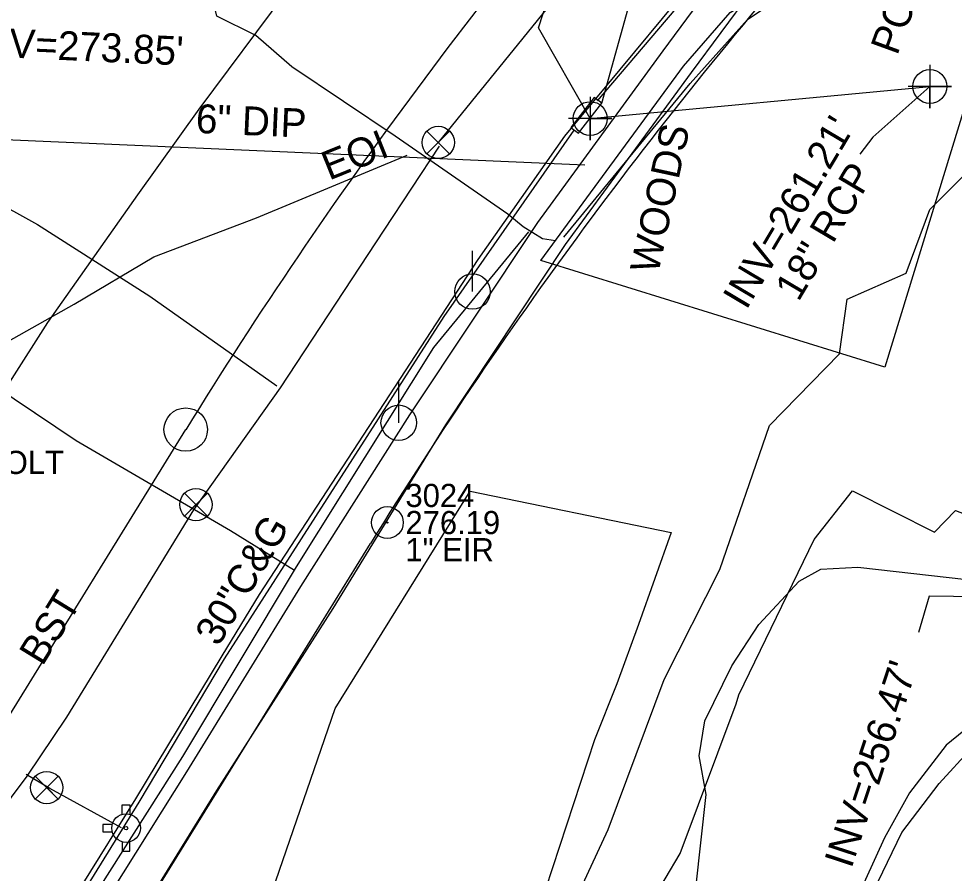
# Model space of a CAD drawing. Extents: x 2100323 to 2109811, y 740376 to 749755.
# Drawn here: x 2105562.4 to 2105691.7, y 743149.3 to 743267.5 of the extents above; entities that cross this region are included whole.
import ezdxf

# ---------------------------------------------------------------- set-up
doc = ezdxf.new("R2010")
doc.units = 0
for name, color, linetype in [('Exist Horizontal Alignment Point', 7, 'Continuous'), ('Exist Hydro Jurisdictional Stream or Body of Water', 7, 'Continuous'), ('Exist Hydro Stream or Body of Water', 7, 'Continuous'), ('Exist Other Culture Located Object Text', 7, 'Continuous'), ('Exist Property Iron Pin CELL', 7, 'Continuous'), ('Exist Property Iron Pin Cogo Comment', 7, 'Continuous'), ('Exist Property Iron Pin Cogo Elevation', 7, 'Continuous'), ('Exist Property Iron Pin Cogo Number', 7, 'Continuous'), ('Exist Right of Way Line', 7, 'Continuous'), ('Exist Roads Curbs', 7, 'Continuous'), ('Exist Roads Curbs Text', 7, 'Continuous'), ('Exist Roads EOP', 7, 'Continuous'), ('Exist Roads EOP Other', 7, 'Continuous'), ('Exist Roads EOP Other Text', 7, 'Continuous'), ('Exist Roads EOT', 7, 'Continuous'), ('Exist Roads Soil', 7, 'Continuous'), ('Exist Structure Minor Drop Inlet', 7, 'Continuous'), ('Exist Structure Minor Drop Inlet Leader', 7, 'Continuous'), ('Exist Structure Minor Pipes RCP 15 Inch Invert', 7, 'Continuous'), ('Exist Structure Minor Pipes RCP 15 Inch Leader', 7, 'Continuous'), ('Exist Structure Minor Pipes RCP 18 Inch', 7, 'Continuous'), ('Exist Structure Minor Pipes RCP 18 Inch Cogo Point CELL', 7, 'Continuous'), ('Exist Structure Minor Pipes RCP 18 Inch Invert', 7, 'Continuous'), ('Exist Structure Minor Pipes RCP 18 Inch Leader', 7, 'Continuous'), ('Exist Survey Centerline', 7, 'Continuous'), ('Exist Utilities Gas UG Line SUE LOS B', 7, 'Continuous'), ('Exist Utilities Gas UG Line SUE LOS B Text', 7, 'Continuous'), ('Exist Utilities Power Pole CELL', 7, 'Continuous'), ('Exist Utilities Sanitary Sewer UG Line', 7, 'Continuous'), ('Exist Utilities Sanitary Sewer UG Line Invert Elevation', 7, 'Continuous'), ('Exist Utilities Sanitary Sewer UG Line Text', 7, 'Continuous'), ('Exist Utilities Water Fire Hydrant CELL', 7, 'Continuous'), ('Exist Utilities Water UG Line SUE LOS B', 7, 'Continuous'), ('Exist Utilities Water Valve CELL', 7, 'Continuous'), ('Exist Vegetation Woods Line', 7, 'Continuous'), ('Exist Vegetation Woods Line Text', 7, 'Continuous')]:
    doc.layers.add(name, color=color, linetype=linetype)

msp = doc.modelspace()

# ---------------------------------------------------------------- linework, layer by layer
at = {"layer": 'Exist Horizontal Alignment Point'}
msp.add_circle((2105585.48, 743210.69), 3, dxfattribs=at)
at = {"layer": 'Exist Hydro Jurisdictional Stream or Body of Water'}
for points in [[(2105611.51, 743083.14), (2105621, 743093.76), (2105619.33, 743109.02), (2105632.97, 743131.85), (2105643.89, 743155.42), (2105651.63, 743176.14), (2105659.31, 743191.36), (2105666.16, 743211.28), (2105675.84, 743221.15), (2105676.89, 743228.75), (2105685.05, 743232.31), (2105688.33, 743241.12), (2105701.55, 743254.3), (2105697.47, 743255.64), (2105700.14, 743260.45)], [(2105661.92, 743174.03), (2105672.32, 743195.52), (2105677.64, 743202.24), (2105688.99, 743196.5), (2105691.89, 743199.49), (2105695.92, 743197.94), (2105701.75, 743199.11), (2105705.8, 743200.96), (2105708.02, 743206.18), (2105706.14, 743212.89), (2105695.44, 743219.72), (2105694.63, 743222.54), (2105697.81, 743239.29), (2105714.74, 743245.18), (2105719.05, 743249.95), (2105724.67, 743252.03)], [(2105624.08, 743074.55), (2105634.72, 743099.14), (2105632.38, 743113.28), (2105634.4, 743121.33), (2105641.37, 743131.06), (2105653.8, 743152.06), (2105661.54, 743172.79)]]:
    msp.add_lwpolyline(points, dxfattribs=at)
at = {"layer": 'Exist Hydro Stream or Body of Water'}
msp.add_lwpolyline([(2105661.54, 743172.79), (2105661.92, 743174.03), (2105661.92, 743174.03)], dxfattribs=at)
at = {"layer": 'Exist Property Iron Pin CELL'}
for radius in [2.2, 0.0707]:
    msp.add_circle((2105613.35, 743197.84), radius, dxfattribs=at)
at = {"layer": 'Exist Right of Way Line'}
msp.add_line((2105546.64, 743090.64), (2105611.01, 743194.93), dxfattribs=at)
msp.add_arc((2106150.96, 742861.67), 634.51, 138.49187, 148.31686, dxfattribs=at)
at = {"layer": 'Exist Roads Curbs'}
for points in [[(2105665.93, 743283.59), (2105661.69, 743278.93), (2105642.35, 743256.16)], [(2105639.14, 743252.1), (2105621.15, 743226.32), (2105590.78, 743179.02), (2105578.98, 743159.19), (2105564.1, 743135.08), (2105550.18, 743112.3), (2105535.32, 743088.03), (2105522.97, 743066.77), (2105512.81, 743045.05), (2105499.41, 743011.11), (2105491.13, 742988.26)]]:
    msp.add_lwpolyline(points, dxfattribs=at)
at = {"layer": 'Exist Roads EOP'}
msp.add_lwpolyline([(2105497.38, 743007.27), (2105512.22, 743045.33), (2105522.46, 743067.04), (2105534.76, 743088.24), (2105546.74, 743107.94), (2105563.57, 743135.49), (2105578.58, 743159.63), (2105590.5, 743179.39), (2105595.7, 743187.88), (2105625.9, 743234.22), (2105637.86, 743251.29), (2105661.05, 743279.27), (2105667.24, 743285.75), (2105678.58, 743289.74), (2105689.8, 743286.23)], dxfattribs=at)
at = {"layer": 'Exist Roads EOP Other'}
for points in [[(2105501.08, 743005.15), (2105511.67, 743033.08), (2105523.99, 743060.6), (2105538.57, 743086.76), (2105554.21, 743112.29), (2105569.83, 743138.17), (2105585.65, 743163.37), (2105601.37, 743188.98), (2105616.47, 743212.73), (2105634.17, 743239.33), (2105651.46, 743263.05), (2105667.68, 743285.04)], [(2105671.76, 743282.25), (2105655.36, 743260.06), (2105637.93, 743236.27), (2105621.39, 743211.36), (2105605.82, 743185.98), (2105589.75, 743160.77), (2105574.04, 743135.31), (2105558.38, 743109.45), (2105542.64, 743084.1), (2105528.3, 743058.34), (2105516.18, 743031.31)]]:
    msp.add_lwpolyline(points, dxfattribs=at)
at = {"layer": 'Exist Roads EOT'}
msp.add_lwpolyline([(2105599.31, 743271.17), (2105587.3, 743254.99), (2105578.82, 743243.14), (2105566.36, 743225.51), (2105556.13, 743209.5), (2105550.57, 743199.82)], dxfattribs=at)
at = {"layer": 'Exist Roads Soil'}
msp.add_lwpolyline([(2105679.85, 743145.42), (2105684.46, 743154.98), (2105689.6, 743161.76), (2105694.1, 743166.65), (2105698.97, 743170.49), (2105704.72, 743173.66), (2105709.92, 743175.46), (2105714.68, 743176.96), (2105721.14, 743180.41), (2105723.19, 743182.52), (2105726.27, 743186.3), (2105728.65, 743191.26), (2105730.83, 743199.74), (2105733.16, 743211.07)], dxfattribs=at)
at = {"layer": 'Exist Structure Minor Drop Inlet'}
msp.add_lwpolyline([(2105638.69, 743252.48), (2105639.75, 743251.69), (2105643, 743255.81), (2105641.93, 743256.61)], close=True, dxfattribs=at)
at = {"layer": 'Exist Structure Minor Drop Inlet Leader'}
msp.add_lwpolyline([(2105643, 743255.81), (2105648.25, 743274.78), (2105650.12, 743280.49)], dxfattribs=at)
at = {"layer": 'Exist Structure Minor Pipes RCP 15 Inch Leader'}
msp.add_lwpolyline([(2105704.96, 743187.43), (2105688.24, 743187.65), (2105686.74, 743182.63)], dxfattribs=at)
at = {"layer": 'Exist Structure Minor Pipes RCP 18 Inch'}
msp.add_line((2105641.39, 743253.7), (2105688.34, 743258.14), dxfattribs=at)
at = {"layer": 'Exist Structure Minor Pipes RCP 18 Inch Cogo Point CELL'}
for points in [[(2105688.34, 743261.14), (2105688.34, 743255.14), (2105688.34, 743258.14), (2105691.34, 743258.14), (2105685.34, 743258.14)], [(2105641.39, 743256.7), (2105641.39, 743250.7), (2105641.39, 743253.7), (2105644.39, 743253.7), (2105638.39, 743253.7)]]:
    msp.add_lwpolyline(points, dxfattribs=at)
for centre in [(2105688.34, 743258.14), (2105641.39, 743253.7)]:
    msp.add_circle(centre, 2.34, dxfattribs=at)
at = {"layer": 'Exist Structure Minor Pipes RCP 18 Inch Leader'}
for points in [[(2105641.39, 743253.7), (2105634.22, 743266.27), (2105636.09, 743271.97)], [(2105688.34, 743258.14), (2105680.45, 743251.14), (2105678.65, 743248.77)]]:
    msp.add_lwpolyline(points, dxfattribs=at)
at = {"layer": 'Exist Survey Centerline'}
msp.add_line((2105521.11, 743106.39), (2105585.48, 743210.69), dxfattribs=at)
msp.add_arc((2106150.96, 742861.67), 664.51, 138.49187, 148.31686, dxfattribs=at)
at = {"layer": 'Exist Utilities Gas UG Line SUE LOS B'}
for points in [[(2105637.76, 743237.29), (2105655.2, 743258.55), (2105663.11, 743267.38), (2105671.15, 743272.86), (2105684.15, 743289.34), (2105692.43, 743305.16), (2105701.77, 743320.11), (2105709.45, 743330.22), (2105721.09, 743346.34), (2105732.81, 743363.21), (2105746.84, 743384.78), (2105760.23, 743407.86), (2105772.32, 743431.51), (2105784.3, 743456.02), (2105794.48, 743477.08), (2105811.39, 743519.6), (2105820.13, 743544.18), (2105827.43, 743569.09), (2105834.93, 743601.88), (2105838.25, 743619.4)], [(2105636.59, 743236.81), (2105634.79, 743237.07), (2105632.12, 743238.71), (2105629.98, 743240.47), (2105614.45, 743251.25), (2105600.17, 743260.85), (2105595.17, 743265.17), (2105589.79, 743267.85), (2105588.91, 743271.66), (2105588.74, 743276.41)], [(2105510.89, 743173.49), (2105519.41, 743175.37), (2105539.69, 743184.72), (2105546.9, 743199.96), (2105548.39, 743206.98), (2105555.87, 743220.05), (2105570.05, 743228.04), (2105581.06, 743234.57), (2105595.25, 743239.96), (2105616.08, 743248.63)], [(2105486.37, 742970.89), (2105495.29, 742995.6), (2105504.58, 743021.08), (2105515.51, 743047.26), (2105530.34, 743077.18), (2105541.64, 743096.9), (2105555.43, 743118.78), (2105585.07, 743165.51), (2105600.79, 743191.74), (2105619.78, 743222.05), (2105632.89, 743238.04)], [(2105600.51, 743191.23), (2105591.68, 743196.71), (2105570.33, 743209.16), (2105558.9, 743216.77), (2105548.66, 743219.25)]]:
    msp.add_lwpolyline(points, dxfattribs=at)
at = {"layer": 'Exist Utilities Power Pole CELL'}
for p, q in [((2105625.12, 743229.78), (2105625.12, 743235.41)), ((2105625.12, 743229.78), (2105625.12, 743229.78)), ((2105614.92, 743211.65), (2105614.92, 743217.28)), ((2105614.92, 743211.65), (2105614.92, 743211.65))]:
    msp.add_line(p, q, dxfattribs=at)
for centre in [(2105625.12, 743229.78), (2105614.92, 743211.65)]:
    msp.add_circle(centre, 2.45, dxfattribs=at)
at = {"layer": 'Exist Utilities Sanitary Sewer UG Line'}
msp.add_line((2105554.64, 743251.06), (2105640.66, 743247.29), dxfattribs=at)
at = {"layer": 'Exist Utilities Water Fire Hydrant CELL'}
msp.add_line((2105577.24, 743155.59), (2105577.24, 743155.59), dxfattribs=at)
for points in [[(2105576.72, 743157.5), (2105576.72, 743158.79), (2105577.75, 743158.79), (2105577.75, 743157.48)], [(2105575.32, 743156.1), (2105574.04, 743156.1), (2105574.04, 743155.08), (2105575.32, 743155.08)], [(2105576.72, 743153.68), (2105576.72, 743152.39), (2105577.75, 743152.39), (2105577.75, 743153.7)]]:
    msp.add_lwpolyline(points, dxfattribs=at)
for radius in [1.98, 0.243]:
    msp.add_circle((2105577.24, 743155.59), radius, dxfattribs=at)
at = {"layer": 'Exist Utilities Water UG Line SUE LOS B'}
msp.add_line((2105636.74, 743270.59), (2105620.39, 743250.39), dxfattribs=at)
for points in [[(2105524.61, 743250.89), (2105526.56, 743250.54), (2105538.55, 743247.33), (2105558.24, 743242.81), (2105565.01, 743239.07), (2105580.52, 743229.13), (2105598.06, 743216.76)], [(2105468.99, 742975.63), (2105477.63, 742992.31), (2105489.99, 743023.15), (2105503.09, 743052.49), (2105518.84, 743086.55), (2105534.78, 743116.15), (2105550.83, 743143.43), (2105557.16, 743154.26), (2105563.58, 743162.79), (2105569.07, 743170.93), (2105586.59, 743199.61), (2105598.6, 743216.49), (2105612.92, 743238.29), (2105620.54, 743249.89)], [(2105576.59, 743155.63), (2105566.72, 743161.07), (2105563.42, 743163.02)]]:
    msp.add_lwpolyline(points, dxfattribs=at)
at = {"layer": 'Exist Utilities Water Valve CELL'}
for points in [[(2105621.96, 743251.98), (2105618.81, 743248.83), (2105620.39, 743250.4), (2105621.96, 743248.83), (2105618.81, 743251.98)], [(2105588.48, 743201.89), (2105585.33, 743198.74), (2105586.9, 743200.32), (2105588.48, 743198.74), (2105585.33, 743201.89)], [(2105567.84, 743162.76), (2105564.69, 743159.61), (2105566.27, 743161.19), (2105567.84, 743159.61), (2105564.69, 743162.76)]]:
    msp.add_lwpolyline(points, dxfattribs=at)
for centre in [(2105620.39, 743250.4), (2105586.9, 743200.32), (2105566.27, 743161.19)]:
    msp.add_circle(centre, 2.23, dxfattribs=at)
at = {"layer": 'Exist Vegetation Woods Line'}
for points in [[(2105682.09, 743219.33), (2105634.58, 743234.07), (2105654.26, 743260.96), (2105660.74, 743268.35), (2105673.54, 743276.08), (2105685.22, 743275.66), (2105692.82, 743274.88), (2105694.74, 743274.62), (2105698.53, 743272.9), (2105682.09, 743219.33)], [(2105597.95, 743148.32), (2105606.14, 743172.12), (2105624.79, 743202.19), (2105652.6, 743196.48), (2105648.07, 743183.76), (2105645.05, 743175.56), (2105641.97, 743167.8), (2105634.23, 743144.18)], [(2105655.98, 743147.29), (2105657.43, 743160.24), (2105656.45, 743165.6), (2105657.21, 743170.43), (2105660.95, 743178.02), (2105664.71, 743183.76), (2105670.25, 743189.72), (2105673.25, 743191.4), (2105678.39, 743191.65), (2105726.02, 743186.3), (2105712.75, 743178.71), (2105707.47, 743176.21), (2105701.22, 743174.48), (2105695.45, 743171.03), (2105690.57, 743167.06), (2105685.53, 743160.49), (2105682.05, 743154.24), (2105678.01, 743145.36), (2105672.62, 743132.44)]]:
    msp.add_lwpolyline(points, dxfattribs=at)

# ---------------------------------------------------------------- texts
at = {"layer": 'Exist Other Culture Located Object Text'}
msp.add_text('POST', height=4, rotation=70.0273, dxfattribs=at).set_placement((2105683.81, 743262.32))
at = {"layer": 'Exist Property Iron Pin Cogo Comment'}
for s, p in [('1"EIR BOLT', (2105545.26, 743204.56)), ('1" EIR', (2105615.85, 743192.49))]:
    msp.add_text(s, height=3.2, dxfattribs=at).set_placement(p)
at = {"layer": 'Exist Property Iron Pin Cogo Elevation'}
msp.add_text('276.19', height=3.2, dxfattribs=at).set_placement((2105615.85, 743196.24))
at = {"layer": 'Exist Property Iron Pin Cogo Number'}
msp.add_text('3024', height=3.2, dxfattribs=at).set_placement((2105615.85, 743199.99))
at = {"layer": 'Exist Roads Curbs Text'}
msp.add_text('30"C&G', height=4, rotation=59.3224, dxfattribs=at).set_placement((2105590.01, 743180.57))
at = {"layer": 'Exist Roads EOP Other Text'}
msp.add_text('BST', height=4, rotation=58.4155, dxfattribs=at).set_placement((2105565.67, 743177.87))
at = {"layer": 'Exist Structure Minor Pipes RCP 15 Inch Invert'}
msp.add_text("INV=256.47'", height=4, rotation=71.8499, dxfattribs=at).set_placement((2105677.49, 743149.89))
at = {"layer": 'Exist Structure Minor Pipes RCP 18 Inch Invert'}
for s, p in [("INV=261.21'", (2105662.97, 743227.13)), ('18" RCP', (2105670.17, 743228.27))]:
    msp.add_text(s, height=4, rotation=59.2512, dxfattribs=at).set_placement(p)
at = {"layer": 'Exist Utilities Gas UG Line SUE LOS B Text'}
msp.add_text('EOI', height=4, rotation=21.9958, dxfattribs=at).set_placement((2105605.3, 743245.11))
at = {"layer": 'Exist Utilities Sanitary Sewer UG Line Invert Elevation'}
msp.add_text("INV=273.85'", height=4, rotation=357.3639, dxfattribs=at).set_placement((2105555.69, 743262.39))
at = {"layer": 'Exist Utilities Sanitary Sewer UG Line Text'}
msp.add_text('6" DIP', height=4, rotation=357.4866, dxfattribs=at).set_placement((2105586.82, 743251.72))
at = {"layer": 'Exist Vegetation Woods Line Text'}
msp.add_text('WOODS', height=4, rotation=77.8136, dxfattribs=at).set_placement((2105650.77, 743232.1))

doc.saveas('drawing.dxf')
